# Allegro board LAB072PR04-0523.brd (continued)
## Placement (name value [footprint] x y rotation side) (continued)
PC521  2200P_0402_25V7K  [C_0402]  58.65 115.27 0 bottom
PC522  390PF_0402_50V7K  [C_0402]  70.67 105.16 270 top
PC523  4700P_0402_50V7K  [C_0402]  69.92 108.13 0 top
PC524  10U_0805_25V6K  [C_0805]  58.2 113.85 0 bottom
PC525  0.22U_0603_16V7K  [C_0603]  64.42 112.71 270 top
PC526  6800P_0402_25V7K  [C_0402]  69.14 103.74 90 bottom
PC527  330P_0402_50V7K  [C_0402]  69.6 108.64 180 bottom
PC528  0.1U_0603_25V7K  [C_0603]  67.08 111.62 270 bottom
PC529  0.068U_0402_16V7K  [C_0402]  71.3 111.31 180 bottom
PC530  0.1U_0402_10V6K  [C_0402]  71.3 110.42 180 top
PC531  33P_0402_50V8J  [C_0402]  69.52 104.65 270 top
PC532  10U_0805_25V6K  [C_0805]  58.22 112.09 0 bottom
PC533  100U_D_20VM_R55M  [C_D]  46.54 112.8 90 bottom
PC534  100U_D_20VM_R55M  [C_D]  53.65 112.8 90 bottom
PC541  330P_0402_50V7K  [C_0402]  72.95 106.1 180 top
PC545  0.082U_0402_16V7K  [C_0402]  70.82 107.01 180 top
PC546  0.01U_0402_50V7K  [C_0402]  72.45 108.08 270 top
PC548  1U_0402_6.3V6K  [C_0402]  62.11 109.27 180 top
PC600  1U_0402_6.3V6K  [C_0402]  46.12 46.12 180 bottom
PC601  0.1U_0402_25V6  [C_0402]  62.41 43.41 90 bottom
PC602  2200P_0402_50V7K  [C_0402]  62.41 43.41 90 top
PC603  10U_0805_25V6K  [C_0805]  63.81 42.51 90 bottom
PC604  10U_0805_25V6K  [C_0805]  60.58 39 180 top
PC605  0.22U_0603_25V7K  [C_0603]  53.97 43.97 90 bottom
PC606  0.01U_0402_16V7K  [C_0402]  47.72 46.03 90 top
PC607  2700P_0402_50V7K  [C_0402]  45.2 47.88 0 bottom
PC608  0.1U_0402_25V6  [C_0402]  50.05 44.57 90 top
PC610  330U_D2_2.5VY_R9M  [C_D2]  67.09 63.68 0 top
PC612  0.01UF_0402_25V7K  [C_0402]  45.08 45.47 270 top
PC613  330U_D2_2.5VY_R9M  [C_D2]  56.98 63.68 180 bottom
PC614  680P_0603_50V7K  [C_0603]  66.67 54.66 180 top
PC615  47P_0402_50V8J  [C_0402]  45.9 49.43 90 top
PC616  0.01U_0402_16V7K  [C_0402]  48 49.28 270 top
PC617  0.22U_0603_25V7K  [C_0603]  53.84 49.58 270 bottom
PC618  0.1U_0402_25V6  [C_0402]  66.98 43.41 90 bottom
PC619  2200P_0402_50V7K  [C_0402]  66.98 43.41 90 top
PC620  10U_0805_25V6K  [C_0805]  65.59 42.51 90 top
PC621  10U_0805_25V6K  [C_0805]  65.59 42.51 90 bottom
PC622  1U_0402_6.3V6K  [C_0402]  47.36 50.92 90 bottom
PC623  330U_D2_2.5VY_R9M  [C_D2]  65.08 63.55 0 bottom
PC625  680P_0603_50V7K  [C_0603]  62.86 54.66 0 top
PC626  1U_0402_6.3V6K  [C_0402]  51.68 46.87 270 top
PC627  10U_0805_25V6K  [C_0805]  63.81 42.51 90 top
PC700  0.022U_0603_50V7K  [C_0603]  17.9 37.39 0 top
PC701  0.1U_0402_25V4Z  [C_0402]  16.76 39.25 270 top
PC702  0.1U_0402_25V6  [C_0402]  37.47 34.93 180 bottom
PC703  2200P_0402_50V7K  [C_0402]  37.47 35.23 180 top
PC704  10U_0805_25V6K  [C_0805]  38.24 36.29 180 bottom
PC705  10U_0805_25V6K  [C_0805]  31.32 40.4 270 bottom
PC706  10U_0805_25V6K  [C_0805]  33.1 40.4 270 top
PC707  10U_0805_25V6K  [C_0805]  33.1 40.4 270 bottom
PC708  10U_0805_25V6K  [C_0805]  38.24 38.06 180 bottom
PC709  10U_0805_25V6K  [C_0805]  38.24 36.63 180 top
PC710  10U_0805_25V6K  [C_0805]  38.24 38.41 180 top
PC711  10U_0805_25V6K  [C_0805]  31.32 40.4 270 top
PC712  0.047U_0603_25V7K~D  [C_0603]  34.01 20.06 270 top
PC716  10U_0805_25V6K  [C_0805]  24.95 21.6 270 bottom
PC717  10U_0805_25V6K  [C_0805]  24.95 21.64 270 top
PC718  100P_0402_50V8J  [C_0402]  35.26 12.7 180 top
PC719  100P_0402_50V8J  [C_0402]  33.46 11.91 90 top
PC720  10U_0805_25V6K  [C_0805]  22.24 26.22 180 top
PC721  10U_0805_25V6K  [C_0805]  22.37 26.28 180 bottom
PC722  1000P_0603_50V7K  [C_0603]  30.69 34.04 90 bottom
PC723  0.1U_0603_25V7K  [C_0603]  94.04 115.31 90 top
PC724  0.1U_0603_25V7K  [C_0603]  34.03 109.4 180 top
PC725  0.1U_0603_25V7K  [C_0603]  15.36 71.05 180 top
PC726  0.1U_0402_25V6  [C_0402]  31.25 15.86 180 top
PC727  0.1U_0402_25V6  [C_0402]  28.5 15.37 270 bottom
PC728  0.1U_0402_25V6  [C_0402]  30.33 14.98 0 top
PC729  1U_0603_25V6K  [C_0603]  30.34 13.9 0 top
PC730  10U_0805_25V6K  [C_0805]  22.37 21.14 180 bottom
PC731  10U_0805_25V6K  [C_0805]  22.37 22.85 180 bottom
PC732  10U_0805_25V6K  [C_0805]  22.37 24.56 180 bottom
PC734  10U_0805_25V6K  [C_0805]  34.98 40.4 270 top
PC745  1U_0603_25V6K  [C_0603]  33.8 15.47 0 top
PC746  0.1U_0402_25V6  [C_0402]  36.63 14.96 90 bottom
PC747  0.1U_0402_25V6  [C_0402]  35.26 16.54 180 top
PC748  1U_0805_25V6K  [C_0805]  36.45 19.27 270 bottom
PC750  0.1U_0402_25V4Z  [C_0402]  34.35 14.43 0 top
PC751  1U_0603_10V6K  [C_0603]  32.12 18.47 180 bottom
PC752  0.1U_0603_25V7K  [C_0603]  22.22 24.51 180 top
PC901  22U_0805_6.3V6M  [C_0805]  99.12 95.05 270 top
PC902  22U_0805_6.3V6M  [C_0805]  97.72 105.12 90 bottom
PC903  22U_0805_6.3V6M  [C_0805]  97.34 101.31 90 bottom
PC904  22U_0805_6.3V6M  [C_0805]  99.24 101.31 90 bottom
PC905  22U_0805_6.3V6M  [C_0805]  124.01 115.28 90 top
PC906  22U_0805_6.3V6M  [C_0805]  101.4 101.31 90 bottom
PC907  22U_0805_6.3V6M  [C_0805]  97.15 95.05 270 top
PC908  22U_0805_6.3V6M  [C_0805]  94.8 101.82 90 top
PC909  22U_0805_6.3V6M  [C_0805]  96.93 107.18 0 top
PC910  22U_0805_6.3V6M  [C_0805]  80.95 113.43 270 bottom
PC911  22U_0805_6.3V6M  [C_0805]  99.5 105.12 90 bottom
PC912  22U_0805_6.3V6M  [C_0805]  99.24 96.32 90 top
PC913  22U_0805_6.3V6M  [C_0805]  101.4 105.12 90 bottom
PC914  22U_0805_6.3V6M  [C_0805]  121.72 115.28 90 bottom
PC915  22U_0805_6.3V6M  [C_0805]  83.79 121.97 0 bottom
PC916  22U_0805_6.3V6M  [C_0805]  83.79 118.42 0 bottom
PC917  22U_0805_6.3V6M  [C_0805]  80.95 113.43 270 top
PC918  22U_0805_6.3V6M  [C_0805]  121.72 115.28 90 top
PC919  22U_0805_6.3V6M  [C_0805]  83.79 120.2 0 bottom
PC920  22U_0805_6.3V6M  [C_0805]  124.01 115.28 90 bottom
PC921  22U_0805_6.3V6M  [C_0805]  97.91 101.3 270 top
PC922  22U_0805_6.3V6M  [C_0805]  99.81 101.3 270 top
PC923  22U_0805_6.3V6M  [C_0805]  97.08 96.32 90 top
PC924  4.7U_0603_6.3V6K  [C_0603]  63.62 87.96 0 top
PC925  4.7U_0603_6.3V6K  [C_0603]  66.79 87.94 0 top
PC926  1U_0402_6.3V  [C_0402]  61.14 82.6 270 top
PC927  1U_0402_6.3V  [C_0402]  63.22 84.76 0 top
PC928  4.7U_0603_6.3V6K  [C_0603]  60.57 88.06 0 top
PC929  1U_0402_6.3V  [C_0402]  62.36 89.74 180 top
PC930  4.7U_0603_6.3V6K  [C_0603]  67.05 86.29 0 top
PC931  1U_0402_6.3V  [C_0402]  67.16 89.72 0 top
PC932  47U_0805_6.3V6M  [C_0805]  63.56 67.53 90 top
PC933  22U_0805_6.3V6M  [C_0805]  57.08 67.49 90 bottom
PC934  4.7U_0805_6.3V6K  [C_0805]  61.52 67.53 90 top
PC935  4.7U_0805_6.3V6K  [C_0805]  59.24 67.53 90 top
PC936  4.7U_0805_6.3V6K  [C_0805]  57.08 67.53 90 top
PC937  4.7U_0805_6.3V6K  [C_0805]  54.92 67.53 90 top
PC938  4.7U_0603_6.3V6K  [C_0603]  60.44 86.16 0 top
PC939  4.7U_0603_6.3V6K  [C_0603]  60.7 84.38 0 top
PC940  4.7U_0603_6.3V6K  [C_0603]  64.03 86.29 0 top
PC941  4.7U_0603_6.3V6K  [C_0603]  63.87 83.11 0 top
PC942  4.7U_0805_6.3V6K  [C_0805]  63.56 67.49 90 bottom
PC949  4.7U_0805_6.3V6K  [C_0805]  61.52 67.49 90 bottom
PC950  4.7U_0805_6.3V6K  [C_0805]  54.92 67.49 90 bottom
PC951  4.7U_0805_6.3V6K  [C_0805]  59.24 67.49 90 bottom
PC952  4.7U_0603_6.3V6K  [C_0603]  64 89.84 0 top
PC953  4.7U_0603_6.3V6K  [C_0603]  65.4 84.38 0 top
PC1000  0.1U_0402_25V6  [C_0402]  40.52 50.47 90 top
PC1001  2200P_0402_50V7K  [C_0402]  41.48 50.5 90 top
PC1002  10U_0805_25V6K  [C_0805]  40.94 50.13 90 bottom
PC1003  10U_0805_25V6K  [C_0805]  40.1 48.67 0 bottom
PC1004  0.1U_0603_25V7K  [C_0603]  44.82 55.17 0 top
PC1005  0.1U_0402_16V7K  [C_0402]  52.94 56.06 0 top
PC1006  1U_0603_6.3V6M  [C_0603]  46.22 56.44 180 top
PC1008  220U_D2_2VY_R17M  [C_D2]  30.03 54.81 270 bottom
PC1009  680P_0402_50V7K  [C_0402]  33.13 47.04 0 top
PD1  -  [TVNST52302AB0_SOT523-3]  19.36 20.5 90 bottom
PD2  -  [TVNST52302AB0_SOT523-3]  19.3 24.72 90 bottom
PD3  AZ5125-01H.R7G_SOD523-2  [AZ5125-01HPR7G_SOD523-2]  16.7 107.5 0 top
PD101  -  [TVNST52302AB0_SOT523-3]  58.09 24.5 180 bottom
PD702  -  [SDMK0340L-7-F_SOD323-2]  41.67 13.85 180 bottom
PD703  -  [SDMK0340L-7-F_SOD323-2]  41.67 12.11 180 bottom
PH500  470K_0402_5%_B25/50 4700K  [R_0402]  60.58 122.54 180 bottom
PH501  10K_0402_5%_B25/50 4250K  [R_0402]  73.38 111.43 0 bottom
PH600  470K_0402_5%_TSM0B474J4702RE  [R_0402]  73.97 42.17 270 top
PJP12  -  [JUMP_43X39]  79.61 52.25 0 bottom
PJP13  -  [JUMP_43X79]  185.89 27.91 90 bottom
PJP14  PAD-OPEN1x1m  [JUMP_43X39]  105.47 18.6 180 top
PJP15  PAD-OPEN1x1m  [JUMP_43X39]  136.53 9.45 180 top
PJP30  PAD-OPEN1x1m  [JUMP_43X39]  84.89 98.94 270 bottom
PJP31  PAD-OPEN1x1m  [JUMP_43X39]  86.03 105.67 270 bottom
PJP100  PAD-OPEN 4x4m  [JUMP_43X118]  41.71 42.05 90 bottom
PJP101  PAD-OPEN 4x4m  [JUMP_43X118]  56.53 18.98 0 bottom
PJP103  PAD-OPEN 4x4m  [JUMP_43X118]  55.64 18.98 0 top
PJP200  -  [JUMP_43X118]  67.44 24.86 270 bottom
PJP201  -  [JUMP_43X118]  72.67 24.86 270 bottom
PJP203  -  [JUMP_43X39]  59.95 26.6 180 bottom
PJP300  -  [JUMP_43X118]  110.29 118.41 0 bottom
PJP400  -  [JUMP_43X79]  176.01 111.33 90 bottom
PJP401  -  [JUMP_43X79]  166.35 119.43 270 bottom
PJP510  -  [JUMP_43X79]  183.95 57.5 270 top
PJP511  -  [JUMP_43X79]  178.36 57.5 270 top
PJP512  -  [JUMP_43X79]  174.77 67.36 0 top
PJP513  -  [JUMP_43X79]  174.77 62.28 0 top
PJP701  PAD-OPEN1x1m  [JUMP_43X39]  30.59 11.28 180 top
PJP1000  -  [JUMP_43X118]  33.96 55.38 90 top
PL1  HCB2012KF-121T50_0805  [TAI-T_HCB2012KF-121T50_2P]  21.5 31.04 180 top
PL2  HCB2012KF-121T50_0805  [TAI-T_HCB2012KF-121T50_2P]  21.5 29.33 180 top
PL3  BLM15AG102SN1D_2P  [MURAT_BLM15AG102SN1D_2P]  18.17 103.32 270 top
PL4  HCB2012KF-121T50_0805  [TAI-T_HCB2012KF-121T50_2P]  28.44 114.65 270 top
PL5  HCB2012KF-121T50_0805  [TAI-T_HCB2012KF-121T50_2P]  26.73 114.65 270 top
PL6  HCB2012KF-121T50_0805  [TAI-T_HCB2012KF-121T50_2P]  23.39 114.65 270 top
PL7  HCB2012KF-121T50_0805  [TAI-T_HCB2012KF-121T50_2P]  25.04 114.65 270 top
PL8  HCB2012KF-121T50_0805  [TAI-T_HCB2012KF-121T50_2P]  21.5 32.76 180 top
PL100  4.7UH_5.5A_20%_7X7X3_M  [L_7X7X3_M_2P]  43.36 38.79 270 bottom
PL101  2.2UH_7.8A_20%_7X7X3_M  [L_7X7X3_M_2P]  43.87 17.47 90 bottom
PL102  HCB2012KF-121T50_0805  [TAI-T_HCB2012KF-121T50_2P]  40.46 27 0 top
PL103  HCB2012KF-121T50_0805  [TAI-T_HCB2012KF-121T50_2P]  40.46 27.1 0 bottom
PL200  1UH_11A_20%_7X7X3_M  [L_7X7X3_M_2P]  66.78 28.1 90 bottom
PL201  HCB2012KF-121T50_0805  [TAI-T_HCB2012KF-121T50_2P]  74.16 40.13 180 bottom
PL301  0.68UH_7.9A_20%_5X5X3_M  [L_5X5X3_M_2P]  102.66 117.59 0 bottom
PL302  HCB2012KF-121T50_0805  [TAI-T_HCB2012KF-121T50_2P]  94.04 111.04 90 bottom
PL501  HCB2012KF-121T50_0805  [TAI-T_HCB2012KF-121T50_2P]  50.72 108.19 180 bottom
PL502  0.15UH_PCMB104T-R15MS0R485_40A_20%  [CYNTE_PCMB104T-R15MS0R485_4P]  67.37 117.69 0 bottom
PL504  HCB2012KF-121T50_0805  [TAI-T_HCB2012KF-121T50_2P]  50.72 109.9 180 bottom
PL600  HCB2012KF-121T50_0805  [TAI-T_HCB2012KF-121T50_2P]  72.33 39.49 0 top
PL601  0.22UH_PCME064T-R22MS0R985_28A_20%  [PANAS_ETQP3W2R2WFN_2P]  68.51 52.4 270 bottom
PL602  0.22UH_PCME064T-R22MS0R985_28A_20%  [PANAS_ETQP3W2R2WFN_2P]  60.51 52.4 270 bottom
PL603  HCB2012KF-121T50_0805  [TAI-T_HCB2012KF-121T50_2P]  72.33 37.77 0 top
PL700  1UH_6.6A_20%_5X5X3_M  [L_5X5X3_M_2P]  36.5 45.14 270 bottom
PL701  2.2UH_12A_20%_10X10X4_M  [L_10X10X4_M_2P]  37.04 25.07 180 bottom
PL1000  HCB2012KF-121T50_0805  [TAI-T_HCB2012KF-121T50_2P]  41.97 48.69 270 top
PL1001  2.2UH_7.8A_20%_7X7X3_M  [L_7X7X3_M_2P]  36.01 48.88 90 bottom
PQ1  FDV301N_G_NL_SOT23-3  [FDV301N_NL_SOT23-3]  19.75 104.98 270 top
PQ2  MMST3904-7-F_SOT323  [MMST3904-7-F_SOT323-3]  24.31 103.43 180 top
PQ3  -  [2N7002KDWH_SOT363-6]  38.65 118.98 180 top
PQ101  -  [MDV1528URH_PDFN33-8-5]  42.96 33.81 180 top
PQ102  -  [FDMC7692S_MLP8-5]  44.68 30.94 0 top
PQ103  -  [MDV1528URH_PDFN33-8-5]  40.98 22.49 0 top
PQ104  -  [FDMC7692S_MLP8-5]  46.64 25.36 180 top
PQ200  -  [MDV1528URH_PDFN33-8-5]  68.33 34.71 270 top
PQ201  -  [FDMC7692S_MLP8-5]  66.78 35.6 180 top
PQ501  -  [CSD87351Q5D_SON8-7]  59.72 117.38 90 bottom
PQ600  -  [MDU1516URH_POWERDFN56-8-5]  72.32 46.54 180 top
PQ601  -  [MDU1511RH_POWERDFN56-8-5]  67.13 52.79 270 top
PQ602  -  [MDU1516URH_POWERDFN56-8-5]  60.92 46.38 180 top
PQ603  -  [MDU1511RH_POWERDFN56-8-5]  62.14 48.41 90 top
PQ701  -  [MDU1516URH_POWERDFN56-8-5]  21.33 41.26 270 bottom
PQ702  -  [MDS1525URH_SO8]  23.74 37.45 90 bottom
PQ703  -  [AO4407AL_SO8]  25.71 29.35 180 bottom
PQ704  -  [SIR472DP-T1-GE3_POWERPAK8-5]  33.83 33.33 270 top
PQ705  -  [SIRA06DP-T1-GE_POWERPAKSO-8-5]  31.68 35.49 180 top
PQ708  -  [DCX124EK-7-F_SC74R-6]  20.3 40.76 90 top
PQ709  -  [DMN65D8LW-7_SOT323-3]  39.17 14.4 90 top
PQ1000  MDV1528URH-1N-PDFN33-8  [SIS412DN-T1-GE3_POWERPAK8-5]  37.48 49.18 270 top
PQ1001  -  [MDV1526URH_PDFN33-8-5]  39.34 51.01 90 top
PR2  100K_0402_5%  [R_0402]  20.96 20.28 180 top
PR3  0_0402_5%  [R_0402]  17.91 104.35 90 top
PR4  2.2K_0402_5%  [R_0402]  20.05 107.51 180 top
PR5  33_0402_5%  [R_0402]  21.94 107.51 180 top
PR6  100K_0402_1%  [R_0402]  20.27 102.4 180 top
PR7  10K_0402_1%  [R_0402]  22.2 102.38 270 top
PR8  15K_0402_1%  [R_0402]  21.22 101.49 90 top
PR9  200K_0402_1%  [R_0402]  36.91 120.21 0 top
PR10  1M_0402_1%  [R_0402]  37.23 115.38 0 top
PR11  1M_0402_1%  [R_0402]  38.14 116.27 180 top
PR12  3.3K_1206_5%~D  [R_1206]  35.78 115.32 90 top
PR13  40.2K_0402_1%  [R_0402]  38.69 121.11 0 top
PR16  4.7K_0805_5%  [R_0805]  27.51 111.81 180 bottom
PR100  0_0402_5%  [R0402_0OHM]  56.65 22.15 180 bottom
PR101  0_0402_5%  [R0402_0OHM]  54.84 22.15 0 top
PR102  2.2K_0402_5%  [R_0402]  55.73 23.04 0 bottom
PR103  2.2_0603_5%  [R_0603]  50.98 33.33 270 top
PR104  150K_0402_1%  [R_0402]  54.89 27.21 0 top
PR105  22K_0402_1%  [R_0402]  54.89 26.04 0 top
PR106  100K_0402_1%  [R_0402]  55.05 25.86 0 bottom
PR107  200K_0402_1%  [R_0402]  55.83 30.63 180 bottom
PR108  8.66K_0402_1%  [R_0402]  54.92 30.63 0 top
PR109  130K_0402_1%  [R_0402]  55.83 29.72 180 top
PR110  0_0402_5%  [R_0402]  54.03 32.64 270 top
PR111  2.2_0603_5%  [R_0603]  50.92 25.39 270 top
PR112  4.7_1206_5%  [R_1206]  45.46 20.75 0 top
PR113  4.7_1206_5%  [R_1206]  44.38 35.68 0 top
PR114  200_0402_5%  [R_0402]  52.89 25.66 270 top
PR115  100K_0402_1%  [R_0402]  54.92 31.73 90 top
PR200  2.2_0603_5%  [R_0603]  62.67 32.63 270 bottom
PR201  0_0402_5%  [R0402_0OHM]  59.36 36.83 270 top
PR202  0_0402_5%  [R0402_0OHM]  55.68 34.85 270 bottom
PR203  4.7_1206_5%  [R_1206]  62.92 32.88 90 top
PR204  10K_0402_1%  [R_0402]  56.94 28.31 270 bottom
PR205  14.7K_0402_1%  [R_0402]  59.35 36.68 270 bottom
PR206  5.1_0603_5%  [R_0603]  58.4 35.91 180 bottom
PR207  8.06K_0402_1%  [R_0402]  56.94 29.2 0 bottom
PR208  887K_0402_1%  [R_0402]  60.25 36.83 270 top
PR300  0_0402_5%  [R0402_0OHM]  104.18 121.39 90 bottom
PR301  1M_0402_1%  [R_0402]  103.29 121.39 90 bottom
PR302  4.7_1206_5%  [R_1206]  103.86 113.52 180 bottom
PR303  0_0603_5%  [R_0603]  95.37 117.21 0 top
PR304  0_0402_5%  [R_0402]  99.22 122.3 270 bottom
PR305  100K_0402_1%  [R_0402]  98.16 122.6 180 bottom
PR306  0_0402_5%  [R_0402]  100.11 121.39 90 bottom
PR307  133K_0402_1%  [R_0402]  93.92 122.99 180 bottom
PR308  10K_0402_5%  [R_0402]  101.51 122.3 270 bottom
PR309  1K_0402_1%  [R_0402]  93.01 122.1 0 bottom
PR310  0_0402_5%  [R_0402]  92.84 118.61 180 bottom
PR400  1.54K_0402_1%  [R_0402]  169.14 113.4 0 bottom
PR401  1.74K_0402_1%  [R_0402]  170.06 115.18 180 bottom
PR402  100K_0402_5%  [R_0402]  179.33 113.97 180 bottom
PR403  59K_0402_1%  [R_0402]  178.41 115.75 0 bottom
PR500  130_0402_1%  [R_0402]  61.19 106.23 0 top
PR504  54.9_0402_1%  [R_0402]  61.19 108.26 0 top
PR505  0_0402_5%  [R0402_0OHM]  61.19 106.23 0 bottom
PR506  0_0402_5%  [R0402_0OHM]  61.19 107.24 0 bottom
PR507  169K_0402_1%  [R_0402]  64.08 108.64 0 bottom
PR508  0_0402_5%  [R0402_0OHM]  61.19 108.26 0 bottom
PR510  0_0402_5%  [R0402_0OHM]  66.83 103.74 90 top
PR511  0_0402_5%  [R0402_0OHM]  65.03 103.74 90 top
PR512  124K_0402_1%  [R_0402]  68.32 111.64 270 bottom
PR513  0_0603_5%  [R_0603]  65.62 111.33 90 top
PR519  1.91K_0402_1%  [R_0402]  65.92 103.74 90 top
PR521  90.9K_0402_1%  [R_0402]  66.49 103.62 180 bottom
PR525  3.83K_0402_1%  [R_0402]  67.75 103.74 90 top
PR528  27.4K_0402_1%  [R_0402]  68.23 104.65 270 bottom
PR533  10_0402_1%  [R_0402]  70.79 106.1 180 top
PR534  4.7_1206_5%  [R_1206]  69.78 119.18 180 top
PR535  200_0402_1%  [R_0402]  69.92 109.15 0 top
PR536  3.65K_0603_1%  [R_0603]  71.49 112.38 180 top
PR537  1.27K_0402_1%  [R_0402]  71.56 105.16 270 top
PR538  2.2_0603_5%  [R_0603]  66.86 111.5 90 top
PR539  3.16K_0402_1%  [R_0402]  68.64 104.65 270 top
PR543  2K_0402_1%  [R_0402]  69.59 106.78 90 bottom
PR545  1.5K_0402_1%  [R_0402]  72.32 109.26 90 top
PR549  11K_0402_1%  [R_0402]  71.3 111.31 180 top
PR551  4.42K_0402_1%  [R_0402]  71.3 110.42 180 bottom
PR558  4.99M_0402_1%  [R_0402]  69.57 109.66 180 bottom
PR600  1K_0402_5%  [R_0402]  48.02 42.85 270 bottom
PR601  0_0402_5%  [R0402_0OHM]  48.91 42.85 270 bottom
PR602  20K_0402_1%  [R_0402]  45.25 43.3 0 bottom
PR603  2K_0402_5%  [R_0402]  46.13 44.25 180 bottom
PR604  20K_0402_1%  [R_0402]  47.08 41.92 90 bottom
PR605  0_0402_5%  [R0402_0OHM]  49.8 42.85 270 bottom
PR606  2.2_0603_5%  [R_0603]  52.57 42.73 0 bottom
PR607  18K_0402_1%  [R_0402]  46.13 45.19 180 bottom
PR608  1K_0402_5%  [R_0402]  50.68 42.85 270 bottom
PR609  0_0603_5%  [R_0603]  66.86 45.96 90 top
PR610  0_0402_5%  [R_0402]  45.2 48.76 0 bottom
PR611  499K_0402_1%  [R_0402]  45.21 47 0 bottom
PR612  0_0402_5%  [R0402_0OHM]  45.2 49.68 0 bottom
PR613  4.7_1206_5%  [R_1206]  70.56 54.96 180 top
PR614  100_0402_1%  [R_0402]  45.01 49.09 270 top
PR615  13K_0402_1%  [R_0402]  53.9 46.34 90 bottom
PR616  0_0402_5%  [R0402_0OHM]  45.18 50.62 0 bottom
PR617  100_0402_1%  [R_0402]  45.18 51.51 0 bottom
PR618  2.2_0603_5%  [R_0603]  52.57 50.68 0 bottom
PR619  0_0603_5%  [R_0603]  55.43 46.87 270 top
PR620  18.7K_0402_1%  [R_0402]  48.23 51.83 270 bottom
PR621  10K_0402_1%  [R_0402]  51.25 51.62 180 bottom
PR622  4.7_1206_5%  [R_1206]  58.92 54.41 0 top
PR623  2.2_0603_5%  [R_0603]  50.16 51.62 0 top
PR624  10K_0402_1%  [R_0402]  49.2 50.9 90 bottom
PR702  0.01_1206_1%  [R_1206_4P-D]  28.16 43.74 0 bottom
PR704  4.02K_0402_1%  [R_0402]  28.83 13.52 180 bottom
PR705  0_0402_5%  [R0402_0OHM]  37.39 16.06 180 top
PR706  10K_0402_1%  [R_0402]  28.5 16.3 90 bottom
PR708  10_1206_5%  [R_1206]  39.3 15.36 90 bottom
PR710  0.01_1206_1%  [R_1206_4P-D]  23.98 22.7 90 bottom
PR711  4.7_1206_5%  [R_1206]  29.9 32.01 0 bottom
PR712  2.2_0603_5%  [R_0603]  32.8 18.66 90 top
PR713  100K_0402_1%  [R_0402]  37.52 11.61 180 top
PR714  0_0402_5%  [R0402_0OHM]  37.46 13.07 180 bottom
PR715  154K_0402_1%  [R_0402]  35.26 11.84 180 top
PR716  0_0402_5%  [R0402_0OHM]  37.52 12.47 180 top
PR717  0_0402_5%  [R0402_0OHM]  37.55 11.23 180 bottom
PR718  0_0402_5%  [R0402_0OHM]  35.18 10.62 180 top
PR719  0_0402_5%  [R0402_0OHM]  44.25 12.88 270 bottom
PR720  0_0402_5%  [R0402_0OHM]  32.36 10.62 0 top
PR721  0_0402_5%  [R0402_0OHM]  45.14 12.88 270 bottom
PR723  10_0603_1%  [R_0603]  28.76 13.83 90 top
PR725  1K_0402_1%  [R_0402]  28.17 12.88 0 top
PR728  0_0402_5%  [R0402_0OHM]  27.92 11.99 0 bottom
PR729  121K_0402_1%  [R_0402]  30.33 12.82 0 top
PR730  4.02K_0402_1%  [R_0402]  37.47 14.02 180 bottom
PR731  4.02K_0402_1%  [R_0402]  37.52 14.2 180 top
PR732  20K_0402_1%  [R_0402]  32.59 11.91 90 top
PR737  4.7_0402_1%  [R_0402]  21.21 36.95 180 top
PR738  0_0402_5%  [R0402_0OHM]  37.39 15.19 180 top
PR739  34K_0402_1%  [R_0402]  37.52 13.34 180 top
PR740  6.49K_0402_1%  [R_0402]  34.35 13.57 0 top
PR741  100K_0402_1%  [R_0402]  42.16 14.48 270 top
PR1000  100K_0402_5%  [R_0402]  53.85 53.37 180 top
PR1001  2.2_0603_5%  [R_0603]  46.22 53.9 180 top
PR1002  45.3K_0402_1%  [R_0402]  53.85 54.26 180 top
PR1003  0_0402_5%  [R0402_0OHM]  53.85 55.15 180 top
PR1004  4.7_1206_5%  [R_1206]  36.06 48.57 180 top
PR1005  470K_0402_1%  [R_0402]  52.94 58.75 0 top
PR1006  9.31K_0402_1%  [R_0402]  52.94 57.84 0 top
PR1007  10K_0402_1%  [R_0402]  52.94 56.95 0 top
PRP1  100_0804_8P4R_5%  [RP_0804_8P4R]  19.55 21.53 180 top
PU100  -  [TPS51285BRUKR_QFN20_3X3]  53.27 27.74 90 top
PU200  -  [G5616ARZ1U_TQFN20_3X3]  59.64 30.73 180 bottom
PU300  -  [SY8206DQNC_QFN10_3X3]  98.25 119.57 180 bottom
PU400  -  [APL5930KAI-TRG_SO8]  171.63 114.29 90 bottom
PU501  -  [ISL95813HRZ-T_QFN20_3X4]  65.07 106.33 0 top
PU600  -  [RT8813AGQW_WQFN24_4X4]  50.98 45.05 180 bottom
PU700  BQ24777RUYR_WQFN28_4x4  [BQ24777RUYR_WQFN28_4X4]  34.69 15.32 180 bottom
PU1000  -  [TPS51212DSCR_SON10_3X3]  51.44 55.06 90 top
Q8  L2N7002LT1G_SOT23-3  [2N7002K_SOT23-3]  184.01 45.27 180 top
Q9  L2N7002LT1G_SOT23-3  [2N7002K_SOT23-3]  178.93 94.07 0 top
Q10  L2N7002LT1G_SOT23-3  [2N7002K_SOT23-3]  163.99 9.96 270 top
Q327  -  [L2N7002WT1G_SC-70-3]  100.77 26.6 270 top
Q330  -  [AO3419L_SOT23-3]  98.2 29.9 270 top
Q2307  L2N7002LT1G_SOT23-3  [2N7002K_SOT23-3]  178.68 45.48 180 top
Q2416  L2N7002LT1G_SOT23-3  [2N7002K_SOT23-3]  190.02 110.9 0 top
QA6  -  [DMN66D0LDW-7_SOT363-6]  181.6 11.47 90 top
QA7  -  [L2N7002WT1G_SC-70-3]  197.02 9.15 270 top
QC1  -  [DMN66D0LDW-7_SOT363-6]  175 91.76 270 top
QD2  -  [L2N7002WT1G_SC-70-3]  139.38 57.46 90 top
QE3  -  [MMST3904-7-F_SOT323-3]  137.34 95.49 90 top
QE7  -  [MMST3904-7-F_SOT323-3]  87.81 69.96 0 bottom
QE8  -  [MMST3904-7-F_SOT323-3]  81.78 104.55 0 bottom
QE9  -  [MMST3904-7-F_SOT323-3]  159.82 21.39 270 top
QE10  -  [MMST3904-7-F_SOT323-3]  168.41 52.43 0 bottom
QE11  -  [L2N7002WT1G_SC-70-3]  122.42 15.29 0 top
QE12  -  [MMST3904-7-F_SOT323-3]  76.89 46.03 180 top
QV5  -  [L2N7002WT1G_SC-70-3]  195.44 58.6 270 top
QV14  -  [DMN66D0LDW-7_SOT363-6]  77.03 100.06 180 top
QV78  -  [L2N7002WT1G_SC-70-3]  77.97 91.11 90 top
QV88  -  [L2N7002WT1G_SC-70-3]  77.65 76.7 180 top
QV89  -  [DMN66D0LDW-7_SOT363-6]  202.71 102.33 270 top
QX1  -  [L2N7002WT1G_SC-70-3]  7.93 73.14 0 top
QX2  -  [SI3457CDV-T1-GE3_TSOP6]  2.53 75.92 0 top
QX3  L2N7002LT1G_SOT23-3  [2N7002K_SOT23-3]  194.39 67.11 90 top
QX4  -  [DMN66D0LDW-7_SOT363-6]  194.35 60.82 0 bottom
QX5  -  [AO3419L_SOT23-3]  10.32 78.48 270 top
R1  100_0402_1%  [R_0402]  109.5 108.96 0 top
R2  100_0402_1%  [R_0402]  110.44 110.1 180 top
R10  100K_0402_5%  [R_0402]  183.04 47.55 0 top
R11  100K_0402_5%  [R_0402]  178.74 91.23 90 top
R16  100K_0402_5%  [R_0402]  181.65 46.28 0 top
R159  100K_0402_5%  [R_0402]  176.14 82.04 270 top
R245  0_0603_5%  [R_0603]  119.69 112.13 270 bottom
R246  0_0603_5%  [R0603_0OHM]  27.42 66.22 0 top
R248  0_0402_5%  [R0402_0OHM]  102.47 94.03 0 bottom
R250  0_0402_5%  [R0402_0OHM]  115.88 109.78 270 top
R251  0_0402_5%  [R0402_0OHM]  118.55 110.37 270 bottom
R252  75_0402_5%  [R_0402]  103.31 95.1 90 bottom
R253  150_0402_1%  [R_0402]  105.92 97.72 180 top
R254  43_0402_1%  [R_0402]  105.67 96.22 180 bottom
R255  10K_0402_5%  [R_0402]  107.42 97.72 0 top
R256  130_0402_1%  [R_0402]  104.76 97.49 0 bottom
R257  0_0402_5%  [R0402_0OHM]  103.51 97.21 180 bottom
R264  0_0603_5%  [R0603_0OHM]  149.05 91.94 270 top
R265  0_0402_5%  [R0402_0OHM]  143.13 74.48 180 top
R267  0_0805_5%  [R0805_0OHM]  136.03 92 180 top
R416  0_0402_5%  [R0402_0OHM]  182.73 66.35 180 top
R944  240_0402_1%  [R_0402]  98.23 32.36 90 top
R990  100K_0402_5%  [R_0402]  102.04 29.44 90 top
R2313  82K_0402_5%  [R_0402]  184.33 49.28 90 top
R2314  22_0603_5%  [R_0603]  177.54 47.68 0 top
R2318  470K_0402_5%  [R_0402]  182.05 49.28 90 top
R2329  10K_0402_5%  [R_0402]  167.62 88.25 0 bottom
R2330  10K_0402_5%  [R_0402]  160.43 77.35 90 top
R2331  2.2K_0402_5%  [R_0402]  176.46 89.16 270 top
R2332  2.2K_0402_5%  [R_0402]  175.57 89.16 270 top
R2333  15_0402_1%  [R_0402]  173.42 88.13 180 bottom
R2334  1K_0402_1%  [R_0402]  175.52 102.73 180 top
R2335  1K_0402_1%  [R_0402]  175.52 103.62 180 top
R2336  22_0402_5%  [R_0402]  150.42 74.97 90 top
R2337  330K_0402_5%  [R_0402]  153.09 76.33 270 top
R2338  330K_0402_5%  [R_0402]  153.09 78.74 270 top
R2339  22_0402_5%  [R_0402]  151.31 74.97 90 top
R2340  10K_0402_5%  [R_0402]  168.28 89.4 180 bottom
R2341  10K_0402_5%  [R_0402]  168.41 90.41 180 bottom
R2342  10K_0402_5%  [R_0402]  173.42 89.91 180 bottom
R2343  10K_0402_5%  [R_0402]  169.17 94.35 180 top
R2344  10K_0402_5%  [R_0402]  168.41 92.19 180 bottom
R2345  10K_0402_5%  [R_0402]  169.17 97.59 180 top
R2347  220K_0402_5%  [R_0402]  142.12 53.71 180 top
R2348  66.5_0402_1%  [R_0402]  143.36 56.12 0 top
R2349  66.5_0402_1%  [R_0402]  143.36 57.01 0 top
R2350  66.5_0402_1%  [R_0402]  143.36 57.9 0 top
R2351  2M_0402_5%  [R_0402]  142.12 54.6 180 top
R2352  66.5_0402_1%  [R_0402]  143.36 58.79 0 top
R2353  1K_0402_5%  [R_0402]  114.74 109.4 90 bottom
R2355  0_0402_5%  [R0402_0OHM]  115.63 109.4 90 bottom
R2356  33_0402_5%  [R_0402]  181.37 20.8 180 top
R2357  33_0402_5%  [R_0402]  181.74 17.2 180 top
R2358  33_0402_5%  [R_0402]  181.74 16.31 180 top
R2359  33_0402_5%  [R_0402]  179.96 27.1 180 bottom
R2360  0_0402_5%  [R0402_0OHM]  175.61 87.82 0 bottom
R2363  0_0402_5%  [R_0402]  169.9 88.89 0 bottom
R2451  0_0402_5%  [R0402_0OHM]  183.14 68.89 180 top
R2484  10K_0402_1%  [R_0402]  86.42 22.58 90 top
R2495  4.7K_0402_5%  [R_0402]  187.52 112.95 90 bottom
R2517  100K_0402_5%  [R_0402]  122.41 19.61 0 top
R2518  47K_0402_5%  [R_0402]  123.32 18.72 180 top
R2521  4.7K_0402_5%  [R_0402]  24.9 66.47 180 top
R2522  4.7K_0402_5%  [R_0402]  24.9 67.43 180 top
R2523  10K_0402_5%  [R_0402]  127.94 111.36 90 bottom
R2524  10K_0402_5%  [R_0402]  128.83 111.36 90 bottom
R2525  10K_0402_5%  [R_0402]  170.03 78.6 0 top
R2526  10K_0402_5%  [R_0402]  170.03 77.71 0 top
R2527  1K_0402_1%  [R_0402]  162.92 79.56 0 bottom
R2528  1K_0402_1%  [R_0402]  169.65 89.72 0 top
R2532  0_0402_5%  [R0402_0OHM]  169.9 88 0 bottom
RA5  470K_0402_5%  [R_0402]  178.41 13.77 0 top
RA6  10K_0402_5%  [R_0402]  180.32 14.02 0 top
RA8  0_0402_5%  [R0402_0OHM]  190.48 26.67 180 top
RA10  10K_0402_5%  [R_0402]  179.33 24.31 180 top
RA19  10K_0402_5%  [R_0402]  177.55 14.66 180 top
RA53  2.2K_0402_5%  [R_0402]  183.57 14.53 180 top
RA55  15_0402_1%  [R_0402]  191.88 21.26 0 top
RA56  15_0402_1%  [R_0402]  191.88 22.15 0 top
RA79  20K_0402_5%  [R_0402]  179.33 14.66 180 top
RA80  1K_0402_1%  [R_0402]  192.51 14.28 0 top
RA81  10K_0402_5%  [R_0402]  178.41 16.44 0 top
RA82  1K_0402_1%  [R_0402]  187.68 13.13 0 top
RA83  10K_0402_5%  [R_0402]  192.16 13.13 180 top
RA84  10K_0402_5%  [R_0402]  189.46 13.13 0 top
RA130  33_0402_5%  [R_0402]  178.54 19.04 0 top
RA165  4.7K_0402_5%  [R_0402]  191.88 20.37 0 top
RA166  4.7K_0402_5%  [R_0402]  194.39 20.4 0 top
RA1109  2.2K_0402_5%  [R_0402]  183.57 15.42 180 top
RA1110  0_0603_5%  [R0603_0OHM]  186.9 28.51 180 top
RA1111  0_0603_5%  [R0603_0OHM]  193.55 11.32 90 top
RA1112  0_0402_5%  [R_0402]  179.05 27.99 0 bottom
RA1113  0_0402_5%  [R_0402]  178.1 21.71 0 top
RA1114  0_0603_5%  [R0603_0OHM]  194.9 22.04 90 top
RA1115  0_0603_5%  [R0603_0OHM]  182.94 12.56 270 top
RA1116  0_0603_5%  [R0603_0OHM]  197.93 7.2 180 top
RA1117  0_0603_5%  [R0603_0OHM]  197.92 20.44 90 top
RA1120  10K_0402_5%  [R_0402]  197.62 16.79 180 top
RA1121  BLM15PX181SN1D_2P  [MURAT_BLM15BB221SN1D_2P]  211.45 5.9 270 top
RA1122  BLM15PX181SN1D_2P  [MURAT_BLM15BB221SN1D_2P]  208.59 3.29 90 top
RA1123  BLM15PX181SN1D_2P  [MURAT_BLM15BB221SN1D_2P]  205.67 3.29 90 top
RA1124  BLM15PX181SN1D_2P  [MURAT_BLM15BB221SN1D_2P]  203.76 3.29 90 top
RA1125  0_0603_5%  [R0603_0OHM]  174.46 26.39 270 top
RA1128  100K_0402_5%  [R_0402]  197.74 10.85 180 top
RA1129  100K_0402_5%  [R_0402]  195.67 17.68 0 top
RA1130  0_0402_5%  [R_0402]  186.75 13.06 90 top
RC1  330K_0402_1%  [R_0402]  167.77 65.84 180 bottom
RC2  330K_0402_1%  [R_0402]  166.86 66.73 0 bottom
RC4  10M_0402_5%  [R_0402]  158.5 78.67 180 top
RC5  20K_0402_5%  [R_0402]  156.57 73.08 0 top
RC6  20K_0402_5%  [R_0402]  156.79 58.09 180 top
RC7  1M_0402_5%  [R_0402]  154.11 77.83 90 top
RC8  1K_0402_5%  [R_0402]  167.9 63.05 180 bottom
RC9  1K_0402_5%  [R_0402]  173.61 81.02 180 top
RC10  1K_0402_5%  [R_0402]  82.15 51.23 0 bottom
RC12  1M_0402_5%  [R_0402]  136.15 111.34 180 bottom
RC13  3.01K_0402_1%  [R_0402]  142.04 108.82 90 top
RC14  1.82K_0402_1%  [R_0402]  119.31 67.57 270 top
RC15  1.82K_0402_1%  [R_0402]  116.46 67.62 180 top
RC16  1.82K_0402_1%  [R_0402]  116.46 66.6 180 top
RC17  2.2_0402_1%  [R_0402]  119.26 65.59 180 top
RC18  2.2_0402_1%  [R_0402]  114.69 68.63 180 top
RC19  2.2_0402_1%  [R_0402]  115.55 65.59 0 top
RC20  1.82K_0402_1%  [R_0402]  120.12 65.59 0 top
RC21  1.82K_0402_1%  [R_0402]  115.55 68.63 0 top
RC22  1.82K_0402_1%  [R_0402]  114.69 65.59 180 top
RC23  24.9_0402_1%  [R_0402]  120.12 64.57 0 top
RC24  24.9_0402_1%  [R_0402]  115.55 69.65 0 top
RC25  24.9_0402_1%  [R_0402]  114.69 64.57 180 top
RC27  10K_0402_5%  [R_0402]  162.23 77.83 90 top
RC28  10K_0402_5%  [R_0402]  170.62 78.68 270 bottom
RC29  10K_0402_5%  [R_0402]  165.99 92.7 180 top
RC32  10K_0402_5%  [R_0402]  168.79 79.49 180 bottom
RC34  10K_0402_5%  [R_0402]  169.17 91.62 180 top
RC36  10K_0402_5%  [R_0402]  169.17 96.57 180 top
RC37  0_0402_5%  [R0402_0OHM]  169.73 77.76 90 bottom
RC38  0_0402_5%  [R0402_0OHM]  180.7 24.31 0 top
RC39  10K_0402_5%  [R_0402]  169.17 90.73 180 top
RC40  0_0402_5%  [R0402_0OHM]  171.01 86.22 180 bottom
RC41  0_0402_5%  [R0402_0OHM]  152.2 75.41 90 top
RC42  0_0402_5%  [R0402_0OHM]  161.35 77.83 90 top
RC43  0_0402_5%  [R0402_0OHM]  91.95 90.38 180 top
RC44  0_0402_5%  [R0402_0OHM]  93.73 91.91 180 top
RC45  0_0402_5%  [R0402_0OHM]  91.95 91.91 180 top
RC46  0_0402_5%  [R0402_0OHM]  84.44 92.41 0 top
RC47  0_0402_5%  [R0402_0OHM]  155 77.83 90 top
RC48  1K_0402_5%  [R_0402]  94.62 76.25 180 top
RC49  0_0402_1%  [R0402_0OHM]  94.62 77.26 180 top
RC50  0_0402_1%  [R0402_0OHM]  94.62 79.56 180 top
RC51  1K_0402_5%  [R_0402]  82.66 81.11 0 top
RC52  0_0402_1%  [R0402_0OHM]  94.62 82.51 180 top
RC53  0_0402_1%  [R0402_0OHM]  94.62 83.49 180 top
RC54  0_0402_1%  [R0402_0OHM]  94.62 84.51 180 top
RC55  0_0402_5%  [R0402_0OHM]  169.17 93.46 180 top
RC56  1K_0402_5%  [R_0402]  94.62 72.73 180 top
RC57  0_0402_5%  [R0402_0OHM]  113.47 109.73 270 top
RC58  49.9_0402_1%  [R_0402]  100.82 97.21 0 bottom
RC59  0_0402_5%  [R0402_0OHM]  104.63 90.99 0 bottom
RC60  62_0402_5%  [R_0402]  102.67 99.44 270 bottom
RC62  0_0402_5%  [R_0402]  104.63 91.87 0 bottom
RC63  0_0402_5%  [R_0402]  101.32 90.1 0 bottom
RC64  1K_0402_5%  [R_0402]  93.71 81.49 0 top
RC65  0_0402_5%  [R_0402]  104.63 90.1 0 bottom
RC66  10K_0402_5%  [R_0402]  116.64 109.45 90 bottom
RC67  56_0402_5%  [R_0402]  104.75 98.48 0 bottom
RC68  200_0402_1%  [R_0402]  112.32 78.62 270 top
RC69  121_0402_1%  [R_0402]  113.21 78.62 270 top
RC70  100_0402_1%  [R_0402]  111.43 78.62 270 top
RC71  24.9_0402_1%  [R_0402]  146.05 108.77 180 top
RC72  0_0402_5%  [R_0402]  130.1 108.82 90 top
RC75  10K_0402_5%  [R_0402]  157.66 110.04 180 top
RC78  0_0402_5%  [R0402_0OHM]  173.68 110.42 180 top
RC80  8.2K_0402_5%  [R_0402]  175.75 108.77 0 top
RC81  0_0402_5%  [R0402_0OHM]  153.22 109.73 270 top
RC84  100K_0402_5%  [R_0402]  154.11 109.73 270 top
RC87  100K_0402_5%  [R_0402]  155 109.73 270 top
RC89  100K_0402_5%  [R_0402]  159.95 110.72 90 bottom
RC90  22.6_0402_1%  [R_0402]  149.61 77.8 0 top
RC91  3.01K_0402_1%  [R_0402]  139.04 108.26 0 bottom
RC92  10K_0402_5%  [R_0402]  152.2 77.83 90 top
RC95  8.2K_0402_5%  [R_0402]  176.66 109.65 180 top
RC97  0_0402_5%  [R0402_0OHM]  168.25 92.51 0 top
RC98  100K_0402_5%  [R_0402]  160.46 109.73 270 top
RC101  49.9_0402_1%  [R_0402]  148.65 75.88 270 top
RC102  10K_0402_5%  [R_0402]  168.41 91.3 180 bottom
RC103  10K_0402_5%  [R_0402]  158.98 74.35 0 top
RC105  10K_0402_5%  [R_0402]  165.08 91.81 0 top
RC106  10K_0402_5%  [R_0402]  173.42 92.57 180 bottom
RC107  0_0402_5%  [R0402_0OHM]  171.49 92 0 top
RC108  100K_0402_5%  [R_0402]  173.42 91.68 180 bottom
RC109  10K_0402_5%  [R_0402]  160.51 79.68 0 bottom
RC111  10K_0402_5%  [R_0402]  173.42 90.79 180 bottom
RC114  1K_0402_5%  [R_0402]  120.45 108.89 90 top
RC116  10K_0402_5%  [R_0402]  172.51 89.02 0 bottom
RC117  10K_0402_5%  [R_0402]  172.7 81.9 0 top
RC118  1K_0402_5%  [R_0402]  160.84 111.64 270 bottom
RC119  10K_0402_5%  [R_0402]  169.17 98.73 180 top
RC120  1K_0402_5%  [R_0402]  165.99 93.59 180 top
RC121  1K_0402_5%  [R_0402]  173.49 86.29 180 bottom
RC126  0_0603_5%  [R0603_0OHM]  148.52 108.32 90 bottom
RC127  0_0402_5%  [R0402_0OHM]  148.01 91.44 270 top
RC129  51_0402_5%  [R_0402]  112.58 109.73 270 top
RC130  1K_0402_1%  [R_0402]  105.54 92.76 180 bottom
RC131  3.01K_0402_1%  [R_0402]  149.66 108.18 90 bottom
RC132  49.9_0402_1%  [R_0402]  106.05 95.05 180 top
RC133  8.2K_0402_1%  [R_0402]  147.38 109.1 270 bottom
RC134  49.9_0402_1%  [R_0402]  145.5 75.11 0 top
RC135  51_0402_1%  [R_0402]  105.54 89.21 180 bottom
RC153  10K_0402_5%  [R_0402]  170.82 89.78 180 bottom
RC183  1K_0402_1%  [R_0402]  107.5 91.67 90 top
RC191  1K_0402_5%  [R_0402]  108.34 90.48 180 top
RC362  1K_0402_1%  [R_0402]  82.66 83.14 0 top
RC363  10K_0402_5%  [R_0402]  117.66 109.78 270 top
RC364  1.5K_0402_5%  [R_0402]  116.77 108.89 90 top
RC365  1K_0402_5%  [R_0402]  119.56 108.89 90 top
RC366  51_0402_5%  [R_0402]  114.18 115.65 90 top
RC367  0_0402_5%  [R0402_0OHM]  79.38 81.84 180 top
RC368  10K_0402_5%  [R_0402]  79.56 96.24 90 top
RC369  10K_0402_5%  [R_0402]  80.57 96.24 90 top
RC370  10K_0402_5%  [R_0402]  78.67 96.24 90 top
RC371  51_0402_5%  [R_0402]  115.09 115.65 90 top
RC372  10K_0402_5%  [R_0402]  3.64 94.66 180 top
RC373  10K_0402_5%  [R_0402]  159.57 109.73 270 top
RC374  10K_0402_5%  [R_0402]  158.68 108.82 90 top
RD1  0_0402_5%  [R0402_0OHM]  95.94 53.6 270 top
RD3  470_0402_5%  [R_0402]  102.8 41.76 90 top
RD4  0_0402_5%  [R0402_0OHM]  139.37 41.25 90 top
RD5  0_0402_5%  [R0402_0OHM]  103.81 41.76 90 top
RD6  10K_0402_5%  [R_0402]  157.28 51.06 270 top
RD7  10K_0402_5%  [R_0402]  158.3 51.06 270 top
RD8  0_0402_5%  [R0402_0OHM]  107.12 42.17 270 top
RD10  0_0402_5%  [R0402_0OHM]  151.06 28.3 90 top
RD12  10K_0402_5%  [R_0402]  172.19 36.38 0 top
RD13  10K_0402_5%  [R_0402]  168.28 37.65 180 top
RE13  100K_0402_5%  [R_0402]  95.69 11.36 90 top
RE14  100K_0402_5%  [R_0402]  103.38 12.37 180 top
RE24  10K_0402_5%  [R_0402]  96.58 22.33 90 top
RE25  100K_0402_5%  [R_0402]  158.35 13.06 180 top
RE26  10_0402_5%  [R_0402]  160.66 12.25 180 top
RE31  100K_0402_5%  [R_0402]  143.95 7.04 90 top
RE32  0_0402_5%  [R0402_0OHM]  135.49 11.1 0 top
RE33  10K_0402_5%  [R_0402]  145.72 7.93 270 top
RE35  10K_0402_5%  [R_0402]  103.38 13.26 180 top
RE38  2.2K_0402_5%  [R_0402]  141.96 18.85 0 top
RE39  100K_0402_5%  [R_0402]  149.28 23.55 270 top
RE45  2.2K_0402_5%  [R_0402]  141.96 17.07 0 top
RE48  10K_0402_5%  [R_0402]  160.66 15.04 180 top
RE50  10K_0402_5%  [R_0402]  12.08 68.63 90 top
RE55  100K_0402_5%  [R_0402]  158.3 16.06 180 top
RE56  8.2K_0402_5%  [R_0402]  152.33 23.17 270 top
RE57  1K_0402_5%  [R_0402]  142.88 13.77 180 top
RE58  0_0402_5%  [R0402_0OHM]  157.46 15.17 0 top
RE61  43_0402_5%  [R_0402]  146.36 22.13 90 top
RE62  0_0402_5%  [R0402_0OHM]  142.68 8.13 270 top
RE63  100K_0402_5%  [R_0402]  140.64 13.77 180 top
RE64  4.7K_0402_5%  [R_0402]  142.88 16.16 180 top
RE65  100K_0402_5%  [R_0402]  151.06 26.16 270 top
RE66  100_0402_1%  [R_0402]  150.17 25.25 90 top
RE67  10K_0402_5%  [R_0402]  162.92 12.5 0 top
RE69  8.2K_0402_5%  [R_0402]  158.37 22.41 180 top
RE70  2.2K_0402_5%  [R_0402]  160.76 19.74 0 top
RE72  10K_0402_5%  [R_0402]  71.51 19.99 270 top
RE74  10K_0402_5%  [R_0402]  72.52 19.99 270 top
RE75  100K_0402_5%  [R_0402]  70.49 19.99 270 top
RE76  49.9_0402_1%  [R_0402]  66.55 19.92 270 top
RE77  1.96K_0402_1%  [R_0402]  157.41 10.34 0 top
RE78  1K_0402_5%  [R_0402]  159.74 16.06 0 top
RE79  33K_0402_5%  [R_0402]  149.53 7.04 90 top
RE80  10_0402_5%  [R_0402]  157.66 18.72 0 top
RE81  10K_0402_5%  [R_0402]  141.96 11.74 0 top
RE82  10K_0402_5%  [R_0402]  140.19 11.74 0 top
RE87  10K_0402_5%  [R_0402]  98.1 23.24 270 top
RE89  100K_0402_5%  [R_0402]  104.25 15.17 0 top
RE90  100K_0402_5%  [R_0402]  102.47 15.17 0 top
RE274  0_0402_5%  [R_0402]  104.25 14.15 0 top
RE275  0_0402_5%  [R0402_0OHM]  103.38 14.15 180 top
RE278  0_0402_5%  [R_0402]  157.46 12.12 0 top
RE279  100K_0402_5%  [R_0402]  94.8 12.26 270 top
RE280  100K_0402_5%  [R_0402]  93.91 12.26 270 top
RL19  75_0603_5%  [R_0603]  197.63 82.88 180 top
RL20  75_0603_5%  [R_0603]  197.63 84.15 180 top
RL27  100K_0402_5%  [R_0402]  185.3 79.62 180 top
RL30  15K_0402_1%  [R_0402]  176.52 88.71 180 bottom
RL31  2.49K_0402_1%  [R_0402]  183.86 91.19 180 bottom
RL33  1K_0402_5%  [R_0402]  175.61 86.93 0 bottom
RL39  75_0603_5%  [R_0603]  197.83 90.41 180 top
RL40  75_0603_5%  [R_0603]  197.83 91.68 180 top
RL41  100K_0402_5%  [R_0402]  181.41 81.03 270 top
RM5  0_0402_5%  [R0402_0OHM]  185.73 52.76 90 top
RM6  0_0402_5%  [R0402_0OHM]  186.62 52.76 90 top
RM7  0_0805_5%  [R_0805]  172.33 56.4 270 top
RM8  100K_0402_5%  [R_0402]  176.66 49.58 180 top
RN5  10K_0402_5%  [R_0402]  181.72 28.3 180 bottom
RP37  10K_8P4R_5%  [RP_0804_8P4R]  171.95 94.66 0 top
RP39  15_0804_8P4R_5%  [RP_0804_8P4R]  173.1 101.54 180 top
RP40  2.2K_0804_8P4R_5%  [RP_0804_8P4R]  172.71 88.31 0 top
RP43  10K_8P4R_5%  [RP_0804_8P4R]  173.1 95.95 180 top
RP44  51_8P4R_5%  [RP_0804_8P4R]  116.51 115.62 90 top
RP48  51_8P4R_5%  [RP_0804_8P4R]  101.21 91.25 0 bottom
RP51  100K_0804_8P4R_5%  [RP_0804_8P4R]  155.87 115.21 90 bottom
RP52  2.2K_0804_8P4R_5%  [RP_0804_8P4R]  153.08 115.21 90 bottom
RP53  2.2K_0804_8P4R_5%  [RP_0804_8P4R]  164.38 111.11 90 bottom
RP55  10K_8P4R_5%  [RP_0804_8P4R]  172.58 84.56 0 top
RP58  470_0804_8P4R_5%  [RP_0804_8P4R]  197.47 70.53 0 top
RP59  470_0804_8P4R_5%  [RP_0804_8P4R]  197.47 65.06 0 top
RP60  10K_8P4R_5%  [RP_0804_8P4R]  173.1 98.74 180 top
RPE3  2.2K_0804_8P4R_5%  [RP_0804_8P4R]  152.46 24.82 90 top
RPE5  100K_0804_8P4R_5%  [RP_0804_8P4R]  155.26 24.88 90 top
RPE6  10K_8P4R_5%  [RP_0804_8P4R]  136.9 12.26 180 top
RPE7  10K_8P4R_5%  [RP_0804_8P4R]  67.83 18.88 90 top
RPE9  100K_0804_8P4R_5%  [RP_0804_8P4R]  102.04 23.93 90 top
RPE10  100K_0804_8P4R_5%  [RP_0804_8P4R]  159.88 10.71 0 top
RPV3  10K_8P4R_5%  [RP_0804_8P4R]  72.95 71.05 90 bottom
RS8  0_0402_5%  [R_0402]  181.72 27.41 180 bottom
RS19  4.7K_0402_5%  [R_0402]  169.85 25.66 270 top
RS21  4.7K_0402_5%  [R_0402]  173.42 26.43 270 top
RS22  0_0402_5%  [R_0402]  167.8 16.36 90 top
RS24  4.7K_0402_5%  [R_0402]  170.74 25.66 270 top
RS25  4.7K_0402_5%  [R_0402]  172.55 24.74 90 top
RS26  0_0402_5%  [R_0402]  146.69 25.96 180 top
RS27  0_0402_5%  [R_0402]  146.69 24.95 180 top
RS30  4.7K_0402_5%  [R_0402]  171.4 16.36 90 top
RS32  4.7K_0402_5%  [R_0402]  170.49 17.27 270 top
RS33  4.7K_0402_5%  [R_0402]  171.66 24.74 90 top
RS35  4.7K_0402_5%  [R_0402]  169.6 17.27 270 top
RS36  4.7K_0402_5%  [R_0402]  168.69 16.36 90 top
RS38  4.7K_0402_5%  [R_0402]  168.94 24.74 90 top
RS39  0_0402_5%  [R0402_0OHM]  138.93 28.64 180 top
RS40  7.5K_0402_1%  [R_0402]  166.25 18.6 180 top
RS41  4.7K_0402_5%  [R_0402]  165.33 17.71 0 top
RS42  4.7K_0402_5%  [R_0402]  173.84 23.15 0 top
RS43  4.7K_0402_5%  [R_0402]  174.76 24.07 180 top
RV18  1M_0402_5%  [R_0402]  192.46 58.02 90 top
RV20  20K_0402_5%  [R_0402]  195.81 56.82 0 top
RV23  10K_0402_5%  [R_0402]  69.27 100.69 90 top
RV24  200_0402_1%  [R_0402]  57.38 72.57 0 bottom
RV25  2.49K_0402_1%  [R_0402]  55.6 72.57 0 bottom
RV26  0_0402_5%  [R_0402]  78.16 99.7 270 top
RV30  0_0402_5%  [R_0402]  74.6 98.78 90 top
RV31  10K_0402_5%  [R_0402]  71.05 100.69 90 top
RV32  75_0402_1%  [R_0402]  200.38 117.54 270 top
RV33  75_0402_1%  [R_0402]  200.58 110.78 90 top
RV34  75_0402_1%  [R_0402]  200.59 104.94 90 top
RV35  2.2K_0402_5%  [R_0402]  202.54 117.78 0 bottom
RV36  2.2K_0402_5%  [R_0402]  200.16 108 180 bottom
RV37  1K_0402_5%  [R_0402]  202.49 109.58 90 bottom
RV38  1K_0402_5%  [R_0402]  202.49 116.59 270 bottom
RV39  10K_0402_5%  [R_0402]  70.16 100.69 90 top
RV40  0_0402_5%  [R_0402]  73.41 78.16 180 top
RV41  2K_0402_1%  [R_0402]  78.34 94.16 0 bottom
RV42  40.2_0402_1%  [R_0402]  60.18 95.3 0 top
RV43  51.1_0402_1%  [R_0402]  53.98 97.21 180 top
RV44  42.2_0402_1%  [R_0402]  53.98 96.32 180 top
RV45  10K_0402_5%  [R_0402]  80.83 83.95 270 top
RV46  60.4_0402_1%  [R_0402]  58.53 92.89 0 top
RV47  8.45K_0402_1%  [R_0402]  80.12 97.46 0 bottom
RV48  10K_0402_5%  [R_0402]  73.56 94.34 90 top
RV49  49.9K_0402_1%  [R_0402]  80.12 96.45 0 bottom
RV51  10K_0402_5%  [R_0402]  75.81 85.83 90 top
RV59  20K_0402_1%  [R_0402]  63.3 100.59 270 top
RV92  100K_0402_5%  [R_0402]  72.7 100.69 90 bottom
RV93  40.2K_0402_1%  [R_0402]  70.21 94.44 90 top
RV94  8.45K_0402_1%  [R_0402]  80.12 95.43 0 bottom
RV95  40.2K_0402_1%  [R_0402]  72.67 94.34 90 top
RV96  40.2K_0402_1%  [R_0402]  71.1 94.44 90 top
RV97  8.45K_0402_1%  [R_0402]  80.12 94.16 0 bottom
RV98  8.45K_0402_1%  [R_0402]  80.12 98.48 0 bottom
RV99  2K_0402_1%  [R_0402]  78.34 98.48 0 bottom
RV103  10K_0402_5%  [R_0402]  78.46 94.16 0 top
RV104  100K_0402_5%  [R_0402]  70.41 96.24 90 top
RV107  10K_0402_5%  [R_0402]  72.5 77.27 0 top
RV108  10K_0402_5%  [R_0402]  74.99 72.57 180 bottom
RV110  1.33K_0402_1%  [R_0402]  33.79 105.97 180 bottom
RV112  1.33K_0402_1%  [R_0402]  37.09 105.97 180 bottom
RV114  10K_0402_5%  [R_0402]  27.87 87.76 270 top
RV117  10K_0402_5%  [R_0402]  52.71 88.06 180 top
RV118  10K_0402_5%  [R_0402]  51.57 92.76 180 top
RV119  10K_0402_5%  [R_0402]  52.71 86.92 180 top
RV122  8.45K_0402_1%  [R_0402]  65.97 99.67 90 top
RV123  8.45K_0402_1%  [R_0402]  64.19 99.67 90 top
RV124  8.45K_0402_1%  [R_0402]  67.49 100.69 90 top
RV125  10K_0402_5%  [R_0402]  74.6 100.69 90 bottom
RV126  2K_0402_1%  [R_0402]  78.34 97.46 0 bottom
RV127  2K_0402_1%  [R_0402]  78.34 95.43 0 bottom
RV128  4.99K_0402_1%  [R_0402]  65.08 100.59 270 top
RV129  4.99K_0402_1%  [R_0402]  68.38 101.6 270 top
RV130  60.4_0402_1%  [R_0402]  57.84 90.55 270 top
RV132  10K_0402_5%  [R_0402]  51.57 93.65 180 top
RV139  1.33K_0402_1%  [R_0402]  32.87 106.86 0 bottom
RV140  0_0402_5%  [R_0402]  79.38 93.14 180 top
RV142  1.33K_0402_1%  [R_0402]  33.79 71.05 180 top
RV143  1.33K_0402_1%  [R_0402]  37.14 85.07 90 top
RV144  1.33K_0402_1%  [R_0402]  36.17 106.86 0 bottom
RV145  162_0402_1%  [R_0402]  36.17 105.08 0 top
RV146  80.6_0402_1%  [R_0402]  36.12 106.02 90 top
RV147  80.6_0402_1%  [R_0402]  37.01 106.02 90 top
RV148  243_0402_1%  [R_0402]  34.73 105.01 90 bottom
RV149  1.33K_0402_1%  [R_0402]  32.87 70.16 0 top
RV150  1.33K_0402_1%  [R_0402]  35.28 85.14 0 top
RV151  162_0402_1%  [R_0402]  35.79 71.94 0 top
RV152  243_0402_1%  [R_0402]  34.17 91.87 180 top
RV153  80.6_0402_1%  [R_0402]  35.74 71 270 top
RV154  80.6_0402_1%  [R_0402]  36.63 71 270 top
RV155  243_0402_1%  [R_0402]  34.73 71.69 270 top
RV156  243_0402_1%  [R_0402]  28.76 85.19 90 bottom
RV157  2K_0402_1%  [R_0402]  78.34 96.45 0 bottom
RV159  0_0402_5%  [R_0402]  181.41 110.02 90 bottom
RV160  100_0402_1%  [R_0402]  193.37 109.49 0 bottom
RV161  2.2K_0402_5%  [R_0402]  189.3 113.86 270 bottom
RV162  2.2K_0402_5%  [R_0402]  188.41 113.86 270 bottom
RV163  0_0402_5%  [R0402_0OHM]  190.06 102.68 270 bottom
RV164  0_0402_5%  [R0402_0OHM]  189.17 102.68 270 bottom
RV169  1K_0402_5%  [R_0402]  196.46 110.66 90 bottom
RV170  39_0402_5%  [R_0402]  193.34 110.42 0 bottom
RV171  39_0402_5%  [R_0402]  197.34 108.13 0 bottom
RV185  0_0402_5%  [R_0402]  90.43 101.78 180 bottom
RV187  10K_0402_5%  [R_0402]  76.71 84 180 top
RV188  10K_0402_5%  [R_0402]  79.25 100.38 180 bottom
RV189  10K_0402_5%  [R_0402]  79.25 99.49 180 bottom
RV190  10K_0402_5%  [R_0402]  73.72 101.6 270 bottom
RV191  1.8K_0402_5%  [R_0402]  73.08 100.69 90 top
RV192  1.8K_0402_5%  [R_0402]  73.97 100.69 90 top
RV193  0_0402_5%  [R_0402]  90.43 100.76 180 bottom
RV195  10K_0402_5%  [R_0402]  75.05 77.32 90 top
RV196  0_0402_5%  [R_0402]  75.94 78.23 270 top
RV208  0_0402_5%  [R_0402]  76.71 84.89 180 top
RV210  1M_0402_5%  [R_0402]  182.36 110.94 270 bottom
RV214  0_0603_5%  [R0603_0OHM]  182.3 111.86 0 top
RV215  0_0402_5%  [R0402_0OHM]  191.07 112.95 90 bottom
RV252  0_0402_5%  [R_0402]  76.34 97.18 0 top
RV253  0_0402_5%  [R_0402]  76.2 101.46 180 top
RV510  1.8K_0402_5%  [R_0402]  71.05 100.57 90 bottom
RV511  1.8K_0402_5%  [R_0402]  70.16 100.57 90 bottom
RV512  1.8K_0402_5%  [R_0402]  71.94 100.69 90 top
RV513  1.8K_0402_5%  [R_0402]  69.27 100.57 90 bottom
RV514  1.8K_0402_5%  [R_0402]  67.49 100.57 90 bottom
RV515  1.8K_0402_5%  [R_0402]  68.38 100.57 90 bottom
RV516  4.7K_0402_5%  [R_0402]  202.35 103.49 0 top
RV517  4.7K_0402_5%  [R_0402]  205.05 103.49 180 top
RV518  10K_0402_5%  [R_0402]  186.59 113.86 270 bottom
RV519  430_0402_1%  [R_0402]  76.95 103.62 180 bottom
RV520  0_0402_5%  [R_0402]  78.1 85.45 90 top
RX2  270K_0402_5%  [R_0402]  5.62 78.83 0 top
RX3  47K_0402_5%  [R_0402]  5.35 74.6 270 top
RX9  10K_0402_5%  [R_0402]  2.21 84.05 90 top
RX12  10K_0402_5%  [R_0402]  192.59 70.49 270 top
RX13  10K_0402_5%  [R_0402]  191.7 70.49 270 top
RX16  2.2K_0402_5%  [R_0402]  196.96 59.49 0 bottom
RX17  2.2K_0402_5%  [R_0402]  196.96 60.38 0 bottom
RX21  0_0402_5%  [R_0402]  12.04 87.97 180 top
RX22  0_0402_5%  [R_0402]  12.04 88.98 180 top
RX23  0_0402_5%  [R_0402]  12.84 95.18 180 top
RX24  0_0402_5%  [R_0402]  12.84 94.29 180 top
RX26  100K_0402_5%  [R_0402]  3.1 84.05 90 top
RX28  0_0603_5%  [R_0603]  12.95 102.73 90 top
RX29  1K_0402_1%  [R_0402]  3.99 84.05 90 top
RX30  100K_0402_5%  [R_0402]  10.96 82.67 0 top
RX31  100K_0402_5%  [R_0402]  15.54 104.22 180 top
RX32  0_0402_5%  [R0402_0OHM]  7.51 102.95 180 top
RX33  0_0402_5%  [R0402_0OHM]  7.51 101.87 180 top
RX34  0_0402_5%  [R0402_0OHM]  7.52 100.7 180 top
RX35  0_0402_5%  [R0402_0OHM]  7.52 99.56 180 top
RX36  0_0402_5%  [R0402_0OHM]  7.55 98.41 180 top
RX37  0_0402_5%  [R0402_0OHM]  7.55 97.27 180 top
SW1  EVQPLHA15_4P  [SW_SMT1-05-A_4P]  172.28 116.67 90 top
SW3  SSAL120100_3P  [SW_SSAL120100_3P]  176.76 81.98 180 bottom
T27  PAD~D  [TPC12]  162.16 86.9 180 bottom
T32  PAD~D  [TPC12]  93.39 15.79 0 top
T38  PAD  [TPC12]  138.22 107.24 0 top
T39  PAD  [TPC12]  110.99 97.6 0 top
T40  PAD  [TPC12]  113.56 97.58 0 top
T41  PAD  [TPC12]  117.17 97.93 0 top
T42  PAD  [TPC12]  110.27 95.26 180 bottom
T43  PAD  [TPC12]  110.67 96.14 0 top
T44  PAD  [TPC12]  108.44 91.63 0 top
T45  PAD  [TPC12]  105.94 93.59 0 top
T46  PAD  [TPC12]  112.82 92.67 0 top
T47  PAD  [TPC12]  110.18 92.12 0 top
T48  PAD  [TPC12]  109.96 93.72 0 top
T49  PAD  [TPC12]  111.65 90.45 180 bottom
T50  PAD  [TPC12]  108.67 95.42 0 top
T51  PAD  [TPC12]  108.07 93.46 0 top
T53  PAD  [TPC12]  149.7 105.35 0 top
T55  PAD  [TPC12]  149.55 79.14 0 top
T56  PAD  [TPC12]  152.68 93.87 0 top
T58  PAD  [TPC12]  151.53 92.97 0 top
T59  PAD  [TPC12]  152.87 91.98 0 top
T87  PAD~D  [TPC12]  203.56 118.85 180 bottom
T94  PAD~D  [TPC12]  181.16 91.87 0 bottom
T95  PAD~D  [TPC12]  179.2 90.11 0 bottom
T96  PAD~D  [TPC12]  57.46 94.92 0 top
T97  PAD  [TPC12]  158.72 91.18 180 bottom
T98  PAD  [TPC12]  159.73 92.24 180 bottom
T99  PAD  [TPC12]  161.04 91.23 180 bottom
T100  PAD~D  [TPC12]  94.48 22.04 0 top
T101  PAD~D  [TPC12]  97.34 21.48 0 top
T102  PAD~D  [TPC12]  93.46 17.3 0 top
T110  PAD~D  [TPC12]  53.14 95.3 0 top
T111  PAD  [TPC12]  108.31 98.77 0 top
T112  PAD  [TPC12]  112.98 100.31 0 top
T113  PAD  [TPC12]  107.52 96.59 0 top
T114  PAD  [TPC12]  111.05 99.98 0 top
T115  PAD  [TPC12]  109.36 96.87 0 top
T116  PAD  [TPC12]  105.95 98.77 0 top
T117  PAD  [TPC12]  154.98 92.13 0 top
T118  PAD~D  [TPC12]  152.4 81.96 0 top
T119  PAD~D  [TPC12]  151.05 82.84 0 top
T120  PAD~D  [TPC12]  148.86 108.21 0 top
T121  PAD~D  [TPC12]  148.47 103.62 0 top
T124  PAD~D  [TPC12]  161.85 94.41 180 bottom
T126  PAD~D  [TPC12]  151.1 89.97 0 top
T127  PAD~D  [TPC12]  160.72 86.65 180 bottom
T128  PAD~D  [TPC12]  161.97 80.58 180 bottom
T129  PAD~D  [TPC12]  135.83 109.1 0 top
T130  PAD~D  [TPC12]  137.15 108.69 0 top
T131  PAD~D  [TPC12]  137.7 110 0 top
T132  PAD~D  [TPC12]  128.83 80.19 0 top
T133  PAD~D  [TPC12]  166.43 97.21 0 top
T134  PAD~D  [TPC12]  129.21 78.67 0 top
T135  PAD~D  [TPC12]  147.98 105.04 0 top
T136  PAD~D  [TPC12]  159.29 86.96 180 bottom
T137  PAD~D  [TPC12]  149.76 84.09 0 top
T138  PAD~D  [TPC12]  141.15 105.91 0 top
T139  PAD~D  [TPC12]  153.32 86.65 0 top
T140  PAD~D  [TPC12]  140.95 110.39 0 top
T141  PAD~D  [TPC12]  151.4 81.08 0 top
T142  PAD~D  [TPC12]  149.06 80.76 0 top
T143  PAD~D  [TPC12]  139.72 107.88 0 top
T144  PAD~D  [TPC12]  148.62 82.81 0 top
T145  PAD~D  [TPC12]  148.04 78.87 0 top
T146  PAD~D  [TPC12]  120.1 82.44 0 top
T147  PAD~D  [TPC12]  117.56 79.44 0 top
T148  PAD~D  [TPC12]  114.19 106.06 180 bottom
T149  PAD~D  [TPC12]  113.34 107.5 180 bottom
T150  PAD~D  [TPC12]  128.92 110.47 0 top
T151  PAD~D  [TPC12]  126.79 108.71 180 bottom
T152  PAD~D  [TPC12]  126.98 110.28 180 bottom
T153  PAD~D  [TPC12]  112.2 97.86 180 bottom
T154  PAD~D  [TPC12]  112.48 96.64 0 top
T155  PAD~D  [TPC12]  138.54 108.73 0 top
T156  PAD~D  [TPC12]  139.53 106.44 0 top
T157  PAD~D  [TPC12]  117.31 80.86 0 top
T158  PAD~D  [TPC12]  120.71 107.3 180 bottom
T159  PAD~D  [TPC12]  153.5 106.36 0 top
T161  PAD~D  [TPC12]  159.25 104.17 180 bottom
T163  PAD~D  [TPC12]  159.72 105.56 180 bottom
T164  PAD~D  [TPC12]  139.54 109.65 0 top
T165  PAD~D  [TPC12]  147.25 108.51 0 top
T166  PAD~D  [TPC12]  114.62 78.98 0 top
T167  PAD~D  [TPC12]  156.53 106.34 0 top
T168  PAD~D  [TPC12]  155.21 106.66 0 top
T169  PAD~D  [TPC12]  117.91 111.84 180 bottom
T170  PAD~D  [TPC12]  116.21 111.31 180 bottom
T171  PAD~D  [TPC12]  160.99 81.18 0 top
T172  PAD~D  [TPC12]  157.08 80.93 0 top
T173  PAD~D  [TPC12]  115.84 80 0 top
T174  PAD~D  [TPC12]  153.86 92.81 0 top
T175  PAD~D  [TPC12]  163.03 98.86 0 top
T176  PAD~D  [TPC12]  153.53 98.99 0 top
T177  PAD~D  [TPC12]  153.85 96.64 0 top
T179  PAD~D  [TPC12]  159.19 100 180 bottom
T180  PAD~D  [TPC12]  160.94 102.21 180 bottom
T181  PAD~D  [TPC12]  158.75 101.58 180 bottom
T182  PAD~D  [TPC12]  160.13 82.98 0 top
T183  PAD~D  [TPC12]  55.63 87.23 0 top
T184  PAD~D  [TPC12]  51.21 90.93 180 bottom
T3861  PAD~D  [TPC12]  175.38 47.61 0 top
T3862  PAD~D  [TPC12]  174.55 49.08 0 top
T4927  PAD~D  [TPC12]  185.6 47.81 180 top
